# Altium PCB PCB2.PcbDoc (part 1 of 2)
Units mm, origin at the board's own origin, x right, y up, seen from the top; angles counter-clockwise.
Board outline 200 x 180 mm, 2 copper layers (Top Layer, Bottom Layer); 324 components, 291 nets, 661 pads, 0 vias.
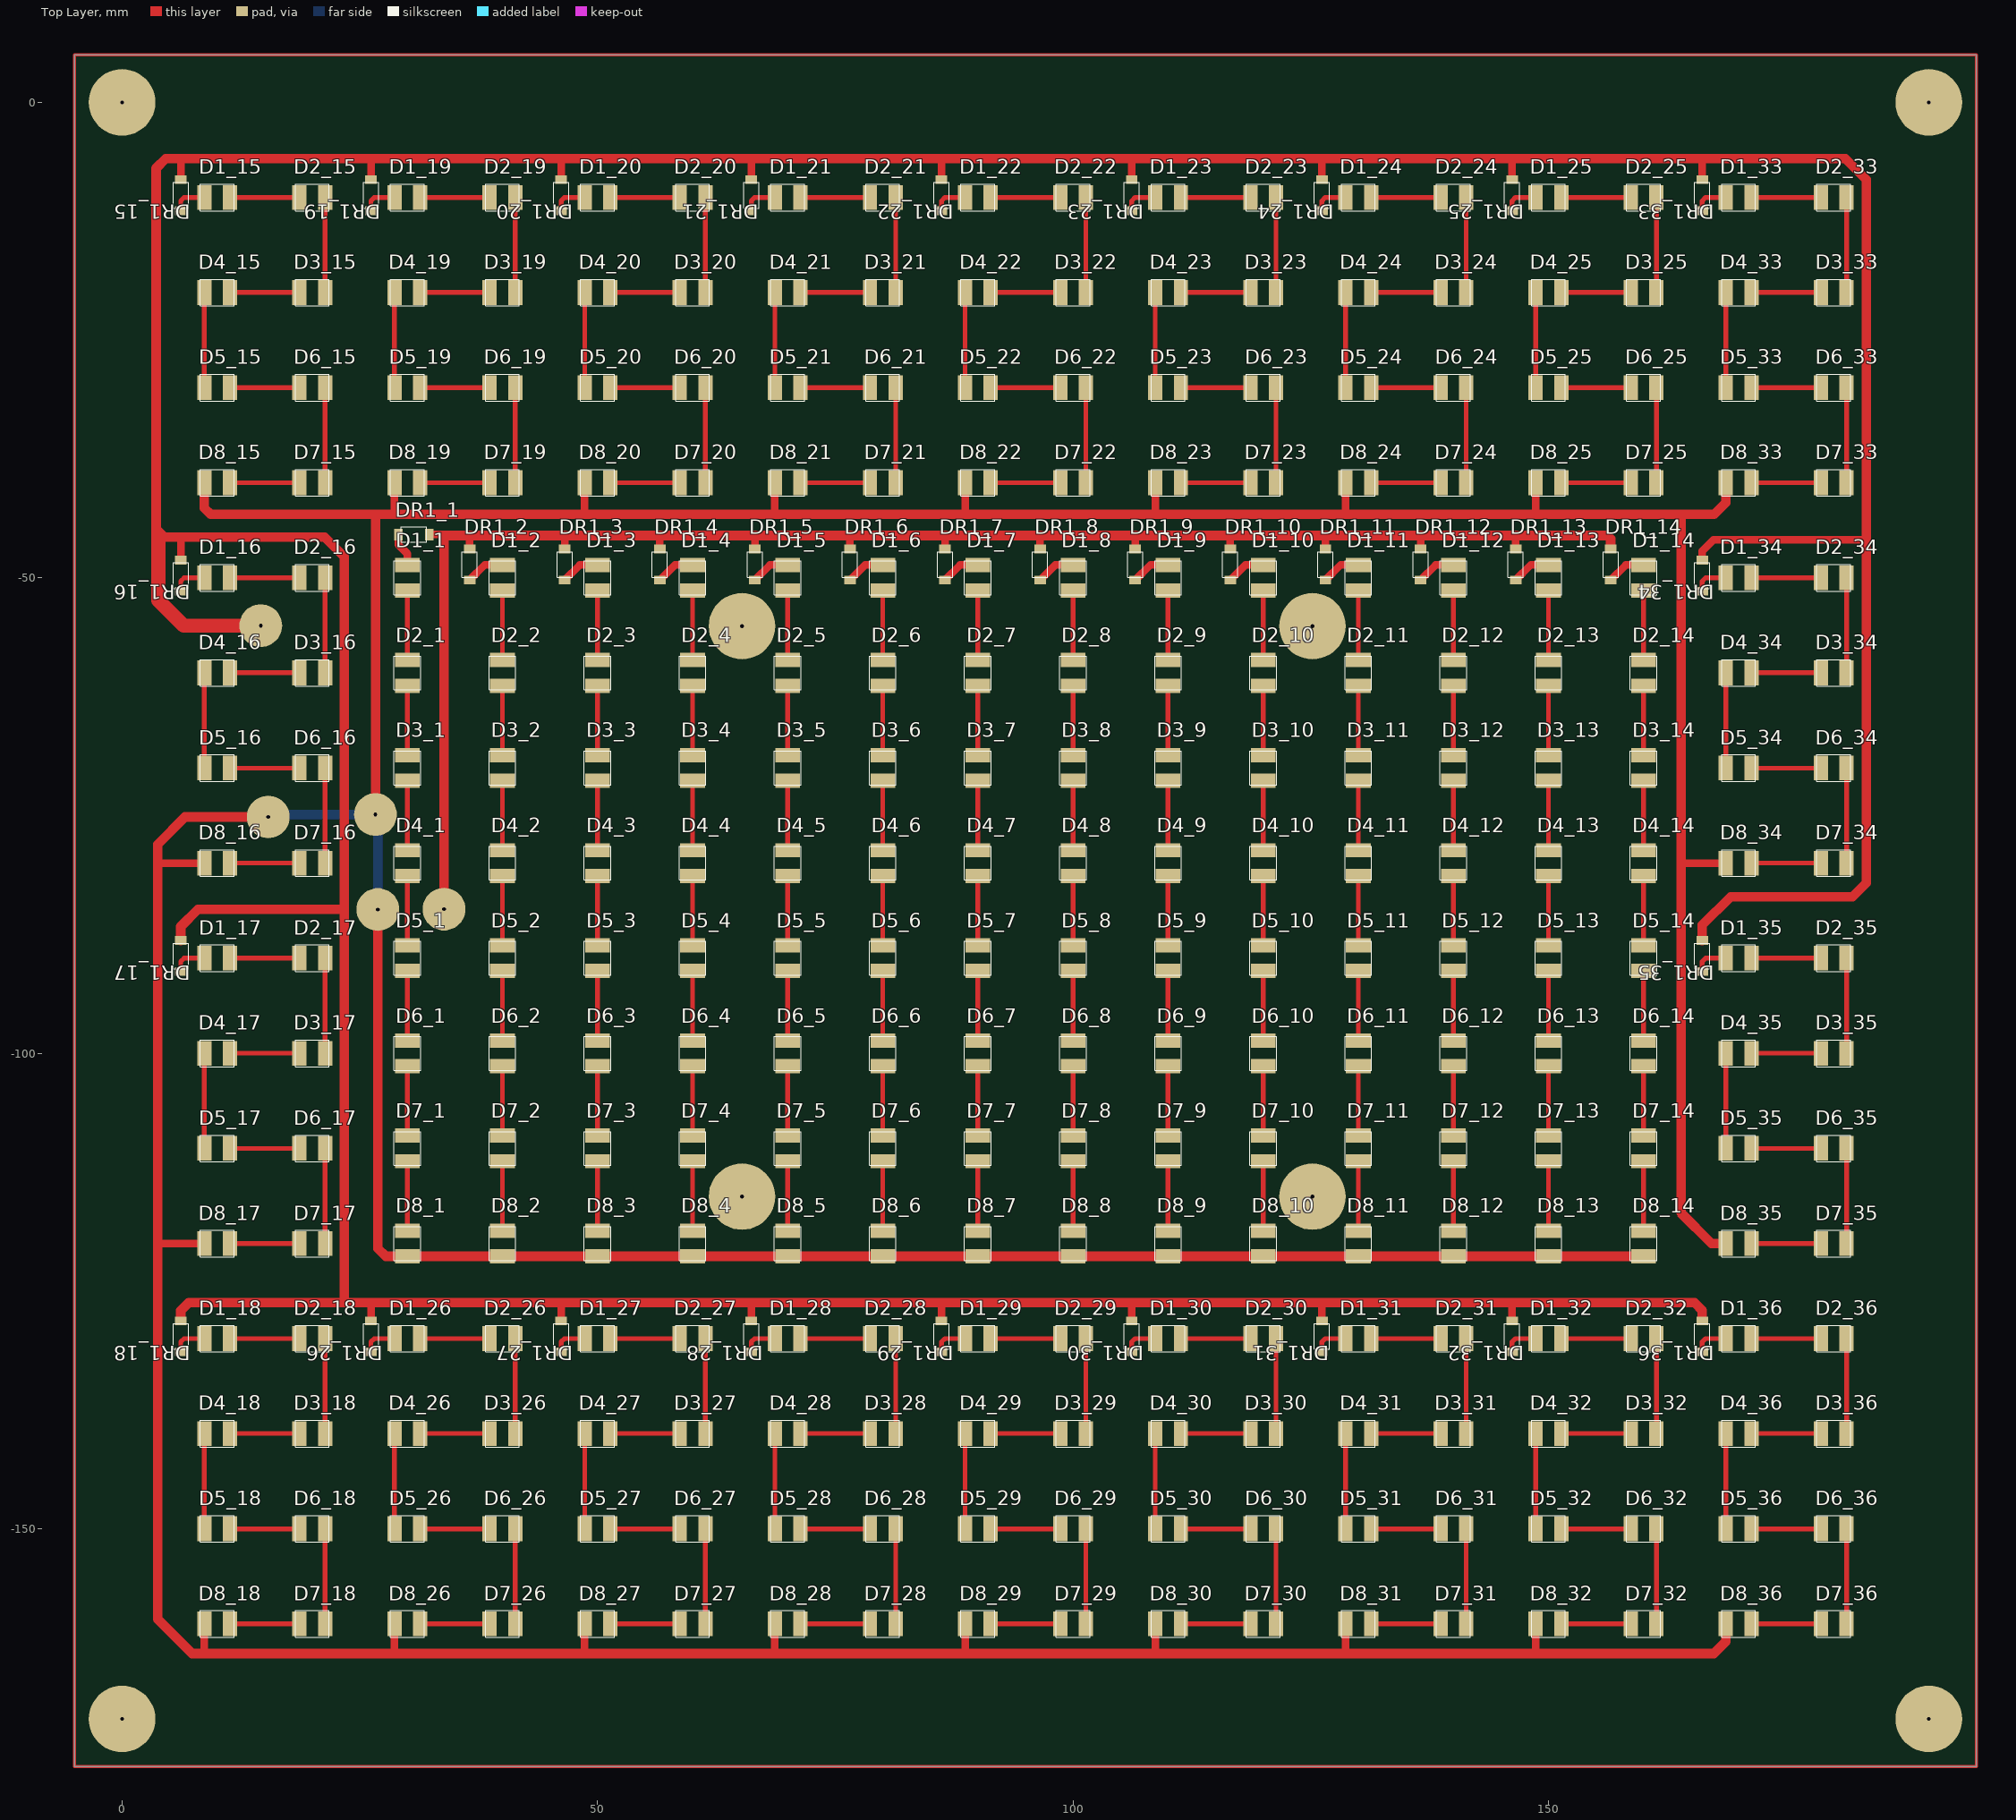
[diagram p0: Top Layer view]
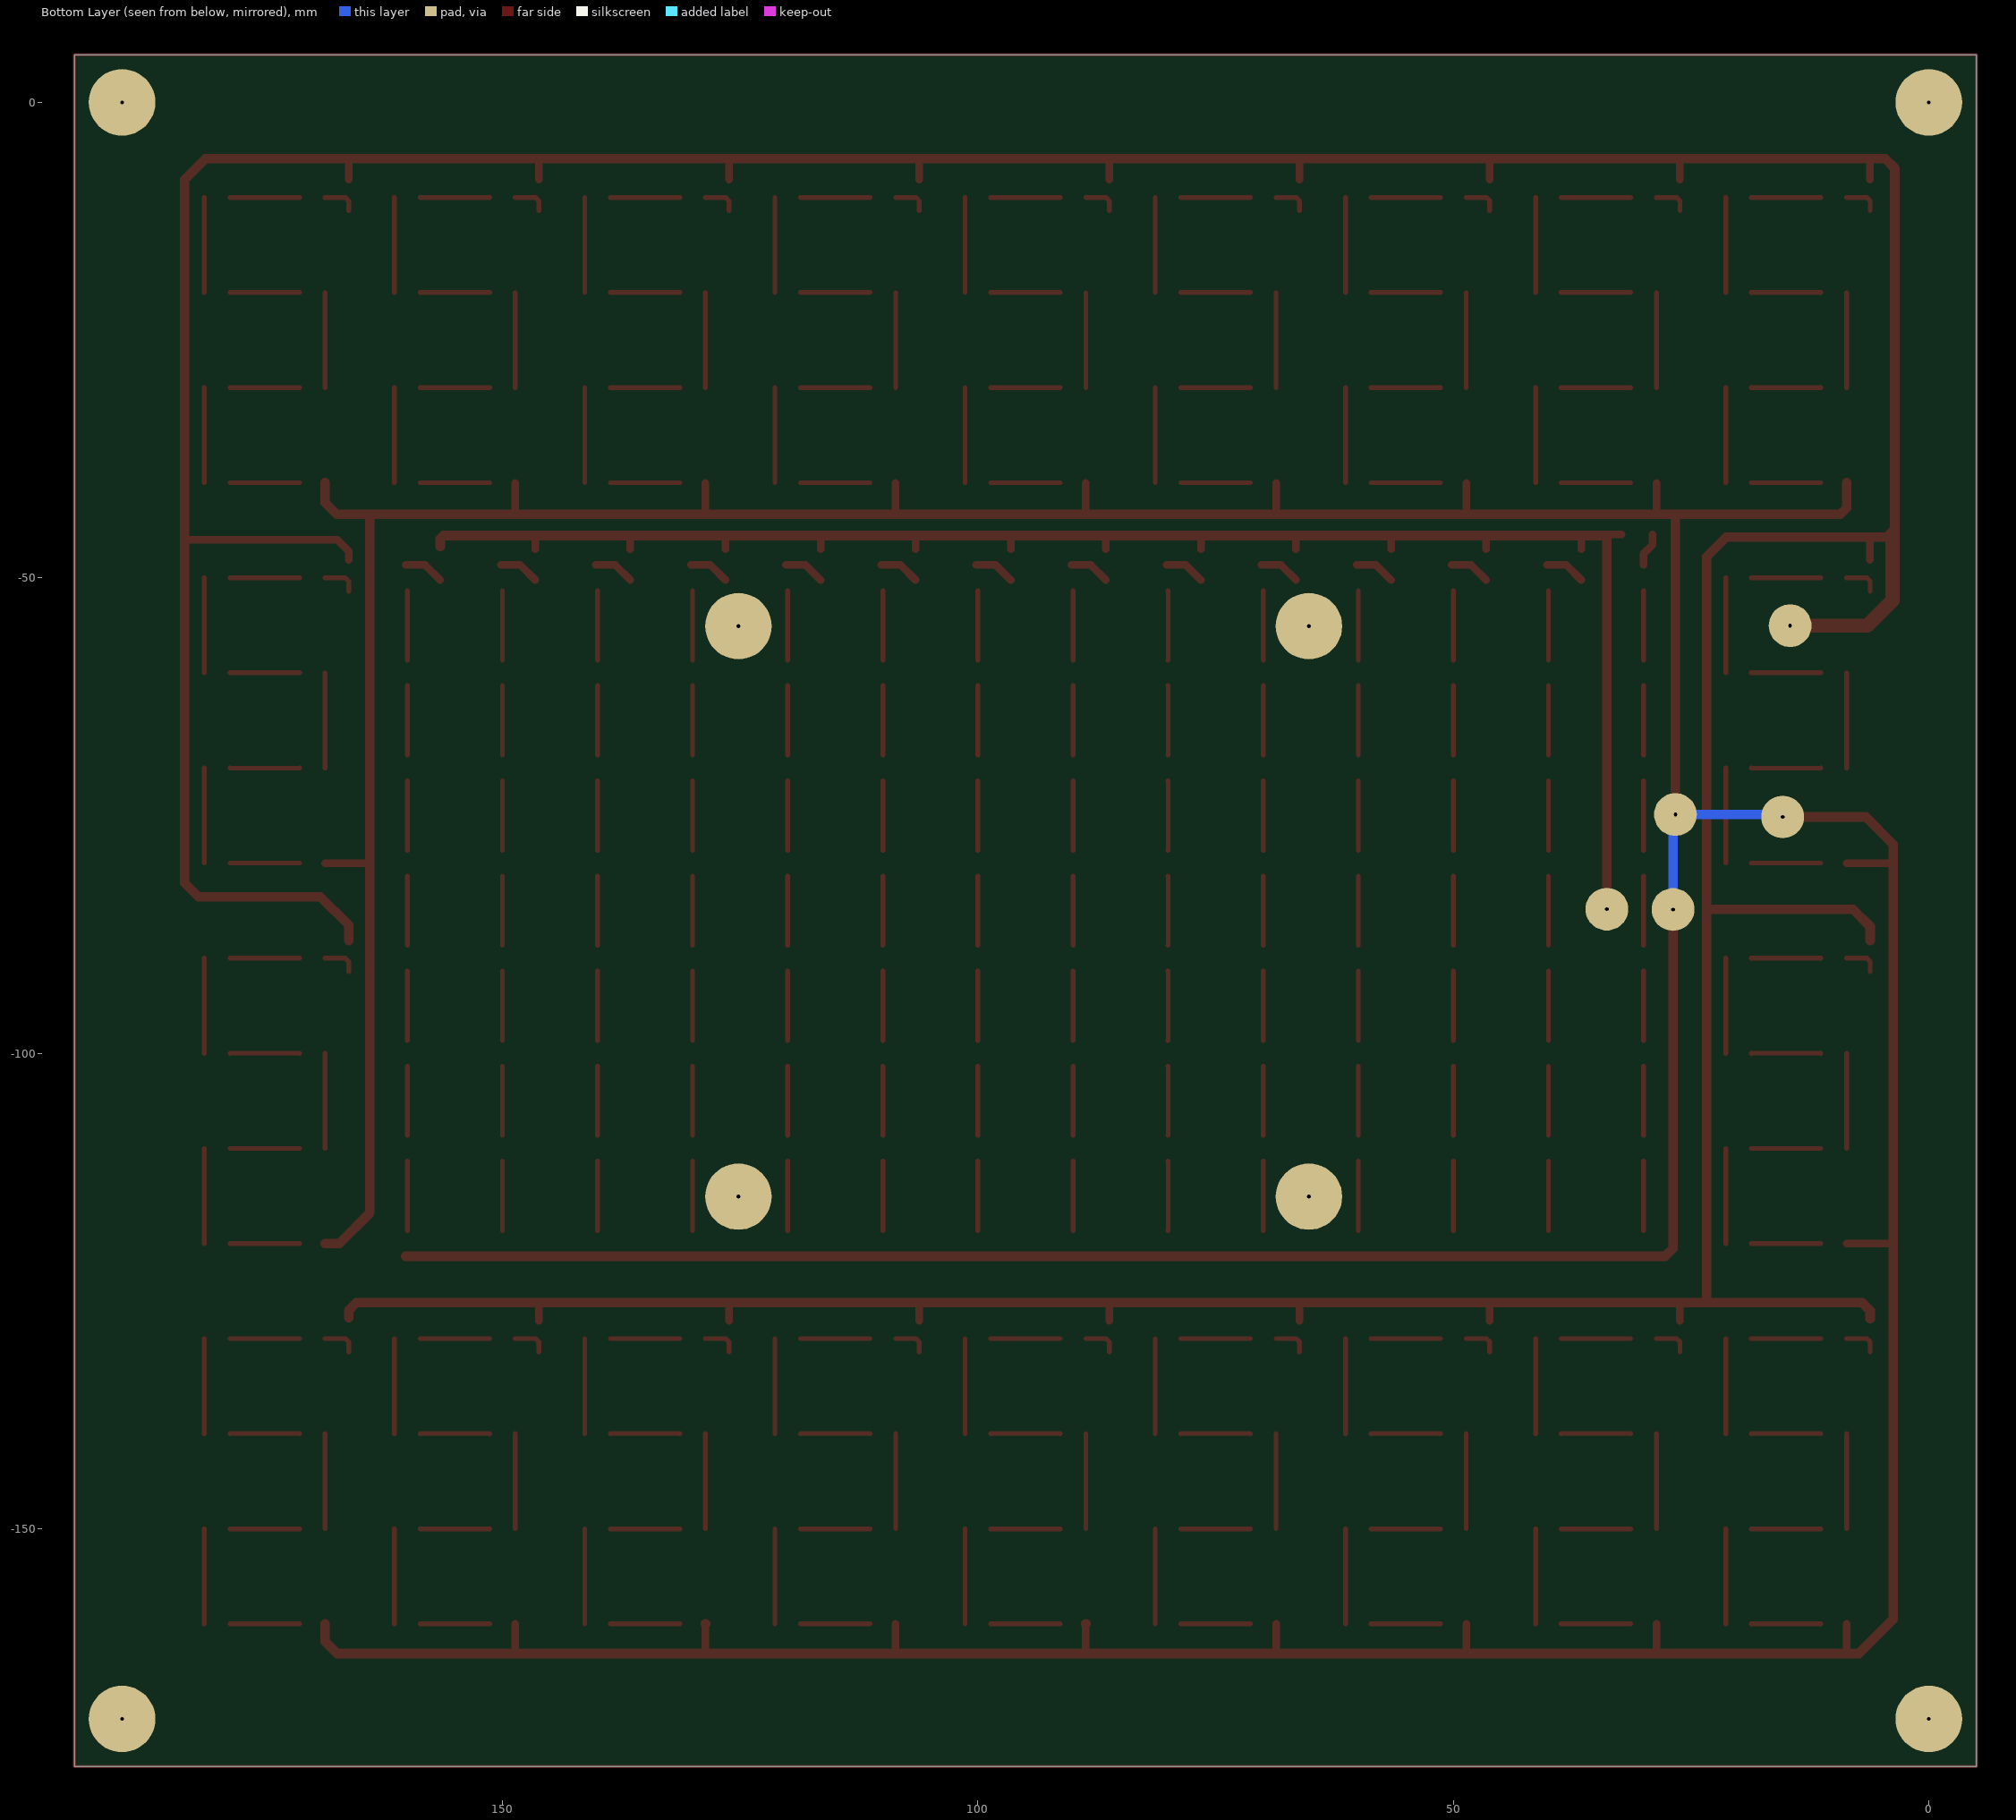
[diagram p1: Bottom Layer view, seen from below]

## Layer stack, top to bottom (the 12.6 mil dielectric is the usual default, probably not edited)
Top Solder: solder mask 0.0102, Solder Resist, Dk 3.5
Top Layer: signal copper 0.0356
Dielectric 1: dielectric 0.32, FR-4, Dk 4.8
Bottom Layer: signal copper 0.0356
Bottom Solder: solder mask 0.0102, Solder Resist, Dk 3.5

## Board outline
195,5 195,-175 -5,-175 -5,5

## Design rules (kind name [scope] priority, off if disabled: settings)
Clearance [All] p1: gap=0.254
PolygonConnect [All] p1: connectstyle=Relief reliefconductorwidth=0.254 reliefentries=4 polygonreliefangle="90 Angle" airgapwidth=0.254
RoomDefinition 36 [InComponentClass('36')] p1: confinementstyle=ConfineIn formatcopy=TRUE lockcomponents=FALSE outline 164.939,-161.797 182.592,-161.797 182.592,-128.371 164.939,-128.371
RoomDefinition 35 [InComponentClass('35')] p2: confinementstyle=ConfineIn formatcopy=TRUE lockcomponents=FALSE outline 164.939,-121.797 182.592,-121.797 182.592,-88.371 164.939,-88.371
RoomDefinition 34 [InComponentClass('34')] p3: confinementstyle=ConfineIn formatcopy=TRUE lockcomponents=FALSE outline 164.939,-81.797 182.592,-81.797 182.592,-48.371 164.939,-48.371
RoomDefinition 33 [InComponentClass('33')] p4: confinementstyle=ConfineIn formatcopy=TRUE lockcomponents=FALSE outline 164.939,-41.797 182.592,-41.797 182.592,-8.371 164.939,-8.371
RoomDefinition 32 [InComponentClass('32')] p5: confinementstyle=ConfineIn formatcopy=TRUE lockcomponents=FALSE outline 144.939,-161.797 162.592,-161.797 162.592,-128.371 144.939,-128.371
RoomDefinition 31 [InComponentClass('31')] p6: confinementstyle=ConfineIn formatcopy=TRUE lockcomponents=FALSE outline 124.939,-161.797 142.592,-161.797 142.592,-128.371 124.939,-128.371
RoomDefinition 30 [InComponentClass('30')] p7: confinementstyle=ConfineIn formatcopy=TRUE lockcomponents=FALSE outline 104.939,-161.797 122.592,-161.797 122.592,-128.371 104.939,-128.371
RoomDefinition 29 [InComponentClass('29')] p8: confinementstyle=ConfineIn formatcopy=TRUE lockcomponents=FALSE outline 84.939,-161.797 102.592,-161.797 102.592,-128.371 84.939,-128.371
RoomDefinition 28 [InComponentClass('28')] p9: confinementstyle=ConfineIn formatcopy=TRUE lockcomponents=FALSE outline 64.939,-161.797 82.592,-161.797 82.592,-128.371 64.939,-128.371
RoomDefinition 27 [InComponentClass('27')] p10: confinementstyle=ConfineIn formatcopy=TRUE lockcomponents=FALSE outline 44.939,-161.797 62.592,-161.797 62.592,-128.371 44.939,-128.371
RoomDefinition 26 [InComponentClass('26')] p11: confinementstyle=ConfineIn formatcopy=TRUE lockcomponents=FALSE outline 24.939,-161.797 42.592,-161.797 42.592,-128.371 24.939,-128.371
RoomDefinition 25 [InComponentClass('25')] p12: confinementstyle=ConfineIn formatcopy=TRUE lockcomponents=FALSE outline 144.939,-41.797 162.592,-41.797 162.592,-8.371 144.939,-8.371
RoomDefinition 24 [InComponentClass('24')] p13: confinementstyle=ConfineIn formatcopy=TRUE lockcomponents=FALSE outline 124.939,-41.797 142.592,-41.797 142.592,-8.371 124.939,-8.371
RoomDefinition 23 [InComponentClass('23')] p14: confinementstyle=ConfineIn formatcopy=TRUE lockcomponents=FALSE outline 104.939,-41.797 122.592,-41.797 122.592,-8.371 104.939,-8.371
RoomDefinition 22 [InComponentClass('22')] p15: confinementstyle=ConfineIn formatcopy=TRUE lockcomponents=FALSE outline 84.939,-41.797 102.592,-41.797 102.592,-8.371 84.939,-8.371
RoomDefinition 21 [InComponentClass('21')] p16: confinementstyle=ConfineIn formatcopy=TRUE lockcomponents=FALSE outline 64.939,-41.797 82.592,-41.797 82.592,-8.371 64.939,-8.371
RoomDefinition 20 [InComponentClass('20')] p17: confinementstyle=ConfineIn formatcopy=TRUE lockcomponents=FALSE outline 44.939,-41.797 62.592,-41.797 62.592,-8.371 44.939,-8.371
RoomDefinition 19 [InComponentClass('19')] p18: confinementstyle=ConfineIn formatcopy=TRUE lockcomponents=FALSE outline 24.939,-41.797 42.592,-41.797 42.592,-8.371 24.939,-8.371
RoomDefinition 18 [InComponentClass('18')] p19: confinementstyle=ConfineIn formatcopy=TRUE lockcomponents=FALSE outline 4.939,-161.797 22.592,-161.797 22.592,-128.371 4.939,-128.371
RoomDefinition 17 [InComponentClass('17')] p20: confinementstyle=ConfineIn formatcopy=TRUE lockcomponents=FALSE outline 4.939,-121.797 22.592,-121.797 22.592,-88.371 4.939,-88.371
RoomDefinition 16 [InComponentClass('16')] p21: confinementstyle=ConfineIn formatcopy=TRUE lockcomponents=FALSE outline 4.939,-81.797 22.592,-81.797 22.592,-48.371 4.939,-48.371
RoomDefinition 15 [InComponentClass('15')] p22: confinementstyle=ConfineIn formatcopy=TRUE lockcomponents=FALSE outline 4.939,-41.797 22.592,-41.797 22.592,-8.371 4.939,-8.371
RoomDefinition 14 [InComponentClass('14')] p23: confinementstyle=ConfineIn formatcopy=TRUE lockcomponents=FALSE outline 155.403,-121.571 162.436,-121.571 162.436,-46.266 155.403,-46.266
RoomDefinition 13 [InComponentClass('13')] p24: confinementstyle=ConfineIn formatcopy=TRUE lockcomponents=FALSE outline 145.403,-121.571 152.436,-121.571 152.436,-46.266 145.403,-46.266
RoomDefinition 12 [InComponentClass('12')] p25: confinementstyle=ConfineIn formatcopy=TRUE lockcomponents=FALSE outline 135.403,-121.571 142.436,-121.571 142.436,-46.266 135.403,-46.266
RoomDefinition 11 [InComponentClass('11')] p26: confinementstyle=ConfineIn formatcopy=TRUE lockcomponents=FALSE outline 125.403,-121.571 132.436,-121.571 132.436,-46.266 125.403,-46.266
RoomDefinition 10 [InComponentClass('10')] p27: confinementstyle=ConfineIn formatcopy=TRUE lockcomponents=FALSE outline 115.403,-121.571 122.436,-121.571 122.436,-46.266 115.403,-46.266
RoomDefinition 9 [InComponentClass('9')] p28: confinementstyle=ConfineIn formatcopy=TRUE lockcomponents=FALSE outline 105.403,-121.571 112.436,-121.571 112.436,-46.266 105.403,-46.266
RoomDefinition 8 [InComponentClass('8')] p29: confinementstyle=ConfineIn formatcopy=TRUE lockcomponents=FALSE outline 95.403,-121.571 102.436,-121.571 102.436,-46.266 95.403,-46.266
RoomDefinition 7 [InComponentClass('7')] p30: confinementstyle=ConfineIn formatcopy=TRUE lockcomponents=FALSE outline 85.403,-121.571 92.436,-121.571 92.436,-46.266 85.403,-46.266
RoomDefinition 6 [InComponentClass('6')] p31: confinementstyle=ConfineIn formatcopy=TRUE lockcomponents=FALSE outline 75.403,-121.571 82.436,-121.571 82.436,-46.266 75.403,-46.266
RoomDefinition 5 [InComponentClass('5')] p32: confinementstyle=ConfineIn formatcopy=TRUE lockcomponents=FALSE outline 65.403,-121.571 72.436,-121.571 72.436,-46.266 65.403,-46.266
RoomDefinition 4 [InComponentClass('4')] p33: confinementstyle=ConfineIn formatcopy=TRUE lockcomponents=FALSE outline 55.403,-121.571 62.436,-121.571 62.436,-46.266 55.403,-46.266
RoomDefinition 3 [InComponentClass('3')] p34: confinementstyle=ConfineIn formatcopy=TRUE lockcomponents=FALSE outline 45.403,-121.571 52.436,-121.571 52.436,-46.266 45.403,-46.266
RoomDefinition 2 [InComponentClass('2')] p35: confinementstyle=ConfineIn formatcopy=TRUE lockcomponents=FALSE outline 35.403,-121.571 42.436,-121.571 42.436,-46.266 35.403,-46.266
RoomDefinition 1 [InComponentClass('1')] p36: confinementstyle=ConfineIn formatcopy=TRUE lockcomponents=FALSE outline 25.403,-121.571 32.436,-121.571 32.436,-46.266 25.403,-46.266
RoutingVias [All] p1: holewidth=0.711 width=1.27 viastyle="Through Hole" minholewidth=0.711 minwidth=1.27 maxholewidth=0.711 maxwidth=1.27
SolderMaskExpansion [All] p1: expansion=0.102
Width [All] p1: maxlimit=1.5 minlimit=0.2 preferedwidth=0.4
30 further rules are at their usual default settings.

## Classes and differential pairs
channel class PCB: 1 2 3 4 5 6 7 8 9 10 11 12 13 14 15 16 17 18 19 20 21 22 23 24 25 26 27 28 29 30 31 32 33 34 35 36
component class 36: D1_36 D2_36 D3_36 D4_36 D5_36 D6_36 D7_36 D8_36 DR1_36
component class 35: D1_35 D2_35 D3_35 D4_35 D5_35 D6_35 D7_35 D8_35 DR1_35
component class 34: D1_34 D2_34 D3_34 D4_34 D5_34 D6_34 D7_34 D8_34 DR1_34
component class 33: D1_33 D2_33 D3_33 D4_33 D5_33 D6_33 D7_33 D8_33 DR1_33
component class 32: D1_32 D2_32 D3_32 D4_32 D5_32 D6_32 D7_32 D8_32 DR1_32
component class 31: D1_31 D2_31 D3_31 D4_31 D5_31 D6_31 D7_31 D8_31 DR1_31
component class 30: D1_30 D2_30 D3_30 D4_30 D5_30 D6_30 D7_30 D8_30 DR1_30
component class 29: D1_29 D2_29 D3_29 D4_29 D5_29 D6_29 D7_29 D8_29 DR1_29
component class 28: D1_28 D2_28 D3_28 D4_28 D5_28 D6_28 D7_28 D8_28 DR1_28
component class 27: D1_27 D2_27 D3_27 D4_27 D5_27 D6_27 D7_27 D8_27 DR1_27
component class 26: D1_26 D2_26 D3_26 D4_26 D5_26 D6_26 D7_26 D8_26 DR1_26
component class 25: D1_25 D2_25 D3_25 D4_25 D5_25 D6_25 D7_25 D8_25 DR1_25
component class 24: D1_24 D2_24 D3_24 D4_24 D5_24 D6_24 D7_24 D8_24 DR1_24
component class 23: D1_23 D2_23 D3_23 D4_23 D5_23 D6_23 D7_23 D8_23 DR1_23
component class 22: D1_22 D2_22 D3_22 D4_22 D5_22 D6_22 D7_22 D8_22 DR1_22
component class 21: D1_21 D2_21 D3_21 D4_21 D5_21 D6_21 D7_21 D8_21 DR1_21
component class 20: D1_20 D2_20 D3_20 D4_20 D5_20 D6_20 D7_20 D8_20 DR1_20
component class 19: D1_19 D2_19 D3_19 D4_19 D5_19 D6_19 D7_19 D8_19 DR1_19
component class 18: D1_18 D2_18 D3_18 D4_18 D5_18 D6_18 D7_18 D8_18 DR1_18
component class 17: D1_17 D2_17 D3_17 D4_17 D5_17 D6_17 D7_17 D8_17 DR1_17
component class 16: D1_16 D2_16 D3_16 D4_16 D5_16 D6_16 D7_16 D8_16 DR1_16
component class 15: D1_15 D2_15 D3_15 D4_15 D5_15 D6_15 D7_15 D8_15 DR1_15
component class 14: D1_14 D2_14 D3_14 D4_14 D5_14 D6_14 D7_14 D8_14 DR1_14
component class 13: D1_13 D2_13 D3_13 D4_13 D5_13 D6_13 D7_13 D8_13 DR1_13
component class 12: D1_12 D2_12 D3_12 D4_12 D5_12 D6_12 D7_12 D8_12 DR1_12
component class 11: D1_11 D2_11 D3_11 D4_11 D5_11 D6_11 D7_11 D8_11 DR1_11
component class 10: D1_10 D2_10 D3_10 D4_10 D5_10 D6_10 D7_10 D8_10 DR1_10
component class 9: D1_9 D2_9 D3_9 D4_9 D5_9 D6_9 D7_9 D8_9 DR1_9
component class 8: D1_8 D2_8 D3_8 D4_8 D5_8 D6_8 D7_8 D8_8 DR1_8
component class 7: D1_7 D2_7 D3_7 D4_7 D5_7 D6_7 D7_7 D8_7 DR1_7
component class 6: D1_6 D2_6 D3_6 D4_6 D5_6 D6_6 D7_6 D8_6 DR1_6
component class 5: D1_5 D2_5 D3_5 D4_5 D5_5 D6_5 D7_5 D8_5 DR1_5
component class 4: D1_4 D2_4 D3_4 D4_4 D5_4 D6_4 D7_4 D8_4 DR1_4
component class 3: D1_3 D2_3 D3_3 D4_3 D5_3 D6_3 D7_3 D8_3 DR1_3
component class 2: D1_2 D2_2 D3_2 D4_2 D5_2 D6_2 D7_2 D8_2 DR1_2
component class 1: D1_1 D2_1 D3_1 D4_1 D5_1 D6_1 D7_1 D8_1 DR1_1

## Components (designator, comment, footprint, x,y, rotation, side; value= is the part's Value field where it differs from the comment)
D1_1 "LED0" UV_LED 30,-50 r270 top (schematic designator D1)
D1_2 "LED0" UV_LED 40,-50 r270 top (schematic designator D1)
D1_3 "LED0" UV_LED 50,-50 r270 top (schematic designator D1)
D1_4 "LED0" UV_LED 60,-50 r270 top (schematic designator D1)
D1_5 "LED0" UV_LED 70,-50 r270 top (schematic designator D1)
D1_6 "LED0" UV_LED 80,-50 r270 top (schematic designator D1)
D1_7 "LED0" UV_LED 90,-50 r270 top (schematic designator D1)
D1_8 "LED0" UV_LED 100,-50 r270 top (schematic designator D1)
D1_9 "LED0" UV_LED 110,-50 r270 top (schematic designator D1)
D1_10 "LED0" UV_LED 120,-50 r270 top (schematic designator D1)
D1_11 "LED0" UV_LED 130,-50 r270 top (schematic designator D1)
D1_12 "LED0" UV_LED 140,-50 r270 top (schematic designator D1)
D1_13 "LED0" UV_LED 150,-50 r270 top (schematic designator D1)
D1_14 "LED0" UV_LED 160,-50 r270 top (schematic designator D1)
D1_15 "LED0" UV_LED 10,-10 r0 top (schematic designator D1)
D1_16 "LED0" UV_LED 10,-50 r0 top (schematic designator D1)
D1_17 "LED0" UV_LED 10,-90 r0 top (schematic designator D1)
D1_18 "LED0" UV_LED 10,-130 r0 top (schematic designator D1)
D1_19 "LED0" UV_LED 30,-10 r0 top (schematic designator D1)
D1_20 "LED0" UV_LED 50,-10 r0 top (schematic designator D1)
D1_21 "LED0" UV_LED 70,-10 r0 top (schematic designator D1)
D1_22 "LED0" UV_LED 90,-10 r0 top (schematic designator D1)
D1_23 "LED0" UV_LED 110,-10 r0 top (schematic designator D1)
D1_24 "LED0" UV_LED 130,-10 r0 top (schematic designator D1)
D1_25 "LED0" UV_LED 150,-10 r0 top (schematic designator D1)
D1_26 "LED0" UV_LED 30,-130 r0 top (schematic designator D1)
D1_27 "LED0" UV_LED 50,-130 r0 top (schematic designator D1)
D1_28 "LED0" UV_LED 70,-130 r0 top (schematic designator D1)
D1_29 "LED0" UV_LED 90,-130 r0 top (schematic designator D1)
D1_30 "LED0" UV_LED 110,-130 r0 top (schematic designator D1)
D1_31 "LED0" UV_LED 130,-130 r0 top (schematic designator D1)
D1_32 "LED0" UV_LED 150,-130 r0 top (schematic designator D1)
D1_33 "LED0" UV_LED 170,-10 r0 top (schematic designator D1)
D1_34 "LED0" UV_LED 170,-50 r0 top (schematic designator D1)
D1_35 "LED0" UV_LED 170,-90 r0 top (schematic designator D1)
D1_36 "LED0" UV_LED 170,-130 r0 top (schematic designator D1)
D2_1 "LED0" UV_LED 30,-60 r270 top (schematic designator D2)
D2_2 "LED0" UV_LED 40,-60 r270 top (schematic designator D2)
D2_3 "LED0" UV_LED 50,-60 r270 top (schematic designator D2)
D2_4 "LED0" UV_LED 60,-60 r270 top (schematic designator D2)
D2_5 "LED0" UV_LED 70,-60 r270 top (schematic designator D2)
D2_6 "LED0" UV_LED 80,-60 r270 top (schematic designator D2)
D2_7 "LED0" UV_LED 90,-60 r270 top (schematic designator D2)
D2_8 "LED0" UV_LED 100,-60 r270 top (schematic designator D2)
D2_9 "LED0" UV_LED 110,-60 r270 top (schematic designator D2)
D2_10 "LED0" UV_LED 120,-60 r270 top (schematic designator D2)
D2_11 "LED0" UV_LED 130,-60 r270 top (schematic designator D2)
D2_12 "LED0" UV_LED 140,-60 r270 top (schematic designator D2)
D2_13 "LED0" UV_LED 150,-60 r270 top (schematic designator D2)
D2_14 "LED0" UV_LED 160,-60 r270 top (schematic designator D2)
D2_15 "LED0" UV_LED 20,-10 r0 top (schematic designator D2)
D2_16 "LED0" UV_LED 20,-50 r0 top (schematic designator D2)
D2_17 "LED0" UV_LED 20,-90 r0 top (schematic designator D2)
D2_18 "LED0" UV_LED 20,-130 r0 top (schematic designator D2)
D2_19 "LED0" UV_LED 40,-10 r0 top (schematic designator D2)
D2_20 "LED0" UV_LED 60,-10 r0 top (schematic designator D2)
D2_21 "LED0" UV_LED 80,-10 r0 top (schematic designator D2)
D2_22 "LED0" UV_LED 100,-10 r0 top (schematic designator D2)
D2_23 "LED0" UV_LED 120,-10 r0 top (schematic designator D2)
D2_24 "LED0" UV_LED 140,-10 r0 top (schematic designator D2)
D2_25 "LED0" UV_LED 160,-10 r0 top (schematic designator D2)
D2_26 "LED0" UV_LED 40,-130 r0 top (schematic designator D2)
D2_27 "LED0" UV_LED 60,-130 r0 top (schematic designator D2)
D2_28 "LED0" UV_LED 80,-130 r0 top (schematic designator D2)
D2_29 "LED0" UV_LED 100,-130 r0 top (schematic designator D2)
D2_30 "LED0" UV_LED 120,-130 r0 top (schematic designator D2)
D2_31 "LED0" UV_LED 140,-130 r0 top (schematic designator D2)
D2_32 "LED0" UV_LED 160,-130 r0 top (schematic designator D2)
D2_33 "LED0" UV_LED 180,-10 r0 top (schematic designator D2)
D2_34 "LED0" UV_LED 180,-50 r0 top (schematic designator D2)
D2_35 "LED0" UV_LED 180,-90 r0 top (schematic designator D2)
D2_36 "LED0" UV_LED 180,-130 r0 top (schematic designator D2)
D3_1 "LED0" UV_LED 30,-70 r270 top (schematic designator D3)
D3_2 "LED0" UV_LED 40,-70 r270 top (schematic designator D3)
D3_3 "LED0" UV_LED 50,-70 r270 top (schematic designator D3)
D3_4 "LED0" UV_LED 60,-70 r270 top (schematic designator D3)
D3_5 "LED0" UV_LED 70,-70 r270 top (schematic designator D3)
D3_6 "LED0" UV_LED 80,-70 r270 top (schematic designator D3)
D3_7 "LED0" UV_LED 90,-70 r270 top (schematic designator D3)
D3_8 "LED0" UV_LED 100,-70 r270 top (schematic designator D3)
D3_9 "LED0" UV_LED 110,-70 r270 top (schematic designator D3)
D3_10 "LED0" UV_LED 120,-70 r270 top (schematic designator D3)
D3_11 "LED0" UV_LED 130,-70 r270 top (schematic designator D3)
D3_12 "LED0" UV_LED 140,-70 r270 top (schematic designator D3)
D3_13 "LED0" UV_LED 150,-70 r270 top (schematic designator D3)
D3_14 "LED0" UV_LED 160,-70 r270 top (schematic designator D3)
D3_15 "LED0" UV_LED 20,-20 r180 top (schematic designator D3)
D3_16 "LED0" UV_LED 20,-60 r180 top (schematic designator D3)
D3_17 "LED0" UV_LED 20,-100 r180 top (schematic designator D3)
D3_18 "LED0" UV_LED 20,-140 r180 top (schematic designator D3)
D3_19 "LED0" UV_LED 40,-20 r180 top (schematic designator D3)
D3_20 "LED0" UV_LED 60,-20 r180 top (schematic designator D3)
D3_21 "LED0" UV_LED 80,-20 r180 top (schematic designator D3)
D3_22 "LED0" UV_LED 100,-20 r180 top (schematic designator D3)
D3_23 "LED0" UV_LED 120,-20 r180 top (schematic designator D3)
D3_24 "LED0" UV_LED 140,-20 r180 top (schematic designator D3)
D3_25 "LED0" UV_LED 160,-20 r180 top (schematic designator D3)
D3_26 "LED0" UV_LED 40,-140 r180 top (schematic designator D3)
D3_27 "LED0" UV_LED 60,-140 r180 top (schematic designator D3)
D3_28 "LED0" UV_LED 80,-140 r180 top (schematic designator D3)
D3_29 "LED0" UV_LED 100,-140 r180 top (schematic designator D3)
D3_30 "LED0" UV_LED 120,-140 r180 top (schematic designator D3)
D3_31 "LED0" UV_LED 140,-140 r180 top (schematic designator D3)
D3_32 "LED0" UV_LED 160,-140 r180 top (schematic designator D3)
D3_33 "LED0" UV_LED 180,-20 r180 top (schematic designator D3)
D3_34 "LED0" UV_LED 180,-60 r180 top (schematic designator D3)
D3_35 "LED0" UV_LED 180,-100 r180 top (schematic designator D3)
D3_36 "LED0" UV_LED 180,-140 r180 top (schematic designator D3)
D4_1 "LED0" UV_LED 30,-80 r270 top (schematic designator D4)
D4_2 "LED0" UV_LED 40,-80 r270 top (schematic designator D4)
D4_3 "LED0" UV_LED 50,-80 r270 top (schematic designator D4)
D4_4 "LED0" UV_LED 60,-80 r270 top (schematic designator D4)
D4_5 "LED0" UV_LED 70,-80 r270 top (schematic designator D4)
D4_6 "LED0" UV_LED 80,-80 r270 top (schematic designator D4)
D4_7 "LED0" UV_LED 90,-80 r270 top (schematic designator D4)
D4_8 "LED0" UV_LED 100,-80 r270 top (schematic designator D4)
D4_9 "LED0" UV_LED 110,-80 r270 top (schematic designator D4)
D4_10 "LED0" UV_LED 120,-80 r270 top (schematic designator D4)
D4_11 "LED0" UV_LED 130,-80 r270 top (schematic designator D4)
D4_12 "LED0" UV_LED 140,-80 r270 top (schematic designator D4)
D4_13 "LED0" UV_LED 150,-80 r270 top (schematic designator D4)
D4_14 "LED0" UV_LED 160,-80 r270 top (schematic designator D4)
D4_15 "LED0" UV_LED 10,-20 r180 top (schematic designator D4)
D4_16 "LED0" UV_LED 10,-60 r180 top (schematic designator D4)
D4_17 "LED0" UV_LED 10,-100 r180 top (schematic designator D4)
D4_18 "LED0" UV_LED 10,-140 r180 top (schematic designator D4)
D4_19 "LED0" UV_LED 30,-20 r180 top (schematic designator D4)
D4_20 "LED0" UV_LED 50,-20 r180 top (schematic designator D4)
D4_21 "LED0" UV_LED 70,-20 r180 top (schematic designator D4)
D4_22 "LED0" UV_LED 90,-20 r180 top (schematic designator D4)
D4_23 "LED0" UV_LED 110,-20 r180 top (schematic designator D4)
D4_24 "LED0" UV_LED 130,-20 r180 top (schematic designator D4)
D4_25 "LED0" UV_LED 150,-20 r180 top (schematic designator D4)
D4_26 "LED0" UV_LED 30,-140 r180 top (schematic designator D4)
D4_27 "LED0" UV_LED 50,-140 r180 top (schematic designator D4)
D4_28 "LED0" UV_LED 70,-140 r180 top (schematic designator D4)
D4_29 "LED0" UV_LED 90,-140 r180 top (schematic designator D4)
D4_30 "LED0" UV_LED 110,-140 r180 top (schematic designator D4)
D4_31 "LED0" UV_LED 130,-140 r180 top (schematic designator D4)
D4_32 "LED0" UV_LED 150,-140 r180 top (schematic designator D4)
D4_33 "LED0" UV_LED 170,-20 r180 top (schematic designator D4)
D4_34 "LED0" UV_LED 170,-60 r180 top (schematic designator D4)
D4_35 "LED0" UV_LED 170,-100 r180 top (schematic designator D4)
D4_36 "LED0" UV_LED 170,-140 r180 top (schematic designator D4)
D5_1 "LED0" UV_LED 30,-90 r270 top (schematic designator D5)
D5_2 "LED0" UV_LED 40,-90 r270 top (schematic designator D5)
D5_3 "LED0" UV_LED 50,-90 r270 top (schematic designator D5)
D5_4 "LED0" UV_LED 60,-90 r270 top (schematic designator D5)
D5_5 "LED0" UV_LED 70,-90 r270 top (schematic designator D5)
D5_6 "LED0" UV_LED 80,-90 r270 top (schematic designator D5)
D5_7 "LED0" UV_LED 90,-90 r270 top (schematic designator D5)
D5_8 "LED0" UV_LED 100,-90 r270 top (schematic designator D5)
D5_9 "LED0" UV_LED 110,-90 r270 top (schematic designator D5)
D5_10 "LED0" UV_LED 120,-90 r270 top (schematic designator D5)
D5_11 "LED0" UV_LED 130,-90 r270 top (schematic designator D5)
D5_12 "LED0" UV_LED 140,-90 r270 top (schematic designator D5)
D5_13 "LED0" UV_LED 150,-90 r270 top (schematic designator D5)
D5_14 "LED0" UV_LED 160,-90 r270 top (schematic designator D5)
D5_15 "LED0" UV_LED 10,-30 r0 top (schematic designator D5)
D5_16 "LED0" UV_LED 10,-70 r0 top (schematic designator D5)
D5_17 "LED0" UV_LED 10,-110 r0 top (schematic designator D5)
D5_18 "LED0" UV_LED 10,-150 r0 top (schematic designator D5)
D5_19 "LED0" UV_LED 30,-30 r0 top (schematic designator D5)
D5_20 "LED0" UV_LED 50,-30 r0 top (schematic designator D5)
D5_21 "LED0" UV_LED 70,-30 r0 top (schematic designator D5)
D5_22 "LED0" UV_LED 90,-30 r0 top (schematic designator D5)
D5_23 "LED0" UV_LED 110,-30 r0 top (schematic designator D5)
D5_24 "LED0" UV_LED 130,-30 r0 top (schematic designator D5)
D5_25 "LED0" UV_LED 150,-30 r0 top (schematic designator D5)
D5_26 "LED0" UV_LED 30,-150 r0 top (schematic designator D5)
D5_27 "LED0" UV_LED 50,-150 r0 top (schematic designator D5)
D5_28 "LED0" UV_LED 70,-150 r0 top (schematic designator D5)
D5_29 "LED0" UV_LED 90,-150 r0 top (schematic designator D5)
D5_30 "LED0" UV_LED 110,-150 r0 top (schematic designator D5)
D5_31 "LED0" UV_LED 130,-150 r0 top (schematic designator D5)
D5_32 "LED0" UV_LED 150,-150 r0 top (schematic designator D5)
D5_33 "LED0" UV_LED 170,-30 r0 top (schematic designator D5)
D5_34 "LED0" UV_LED 170,-70 r0 top (schematic designator D5)
D5_35 "LED0" UV_LED 170,-110 r0 top (schematic designator D5)
D5_36 "LED0" UV_LED 170,-150 r0 top (schematic designator D5)
D6_1 "LED0" UV_LED 30,-100 r270 top (schematic designator D6)
D6_2 "LED0" UV_LED 40,-100 r270 top (schematic designator D6)
D6_3 "LED0" UV_LED 50,-100 r270 top (schematic designator D6)
D6_4 "LED0" UV_LED 60,-100 r270 top (schematic designator D6)
D6_5 "LED0" UV_LED 70,-100 r270 top (schematic designator D6)
D6_6 "LED0" UV_LED 80,-100 r270 top (schematic designator D6)
D6_7 "LED0" UV_LED 90,-100 r270 top (schematic designator D6)
D6_8 "LED0" UV_LED 100,-100 r270 top (schematic designator D6)
D6_9 "LED0" UV_LED 110,-100 r270 top (schematic designator D6)
D6_10 "LED0" UV_LED 120,-100 r270 top (schematic designator D6)
D6_11 "LED0" UV_LED 130,-100 r270 top (schematic designator D6)
D6_12 "LED0" UV_LED 140,-100 r270 top (schematic designator D6)
D6_13 "LED0" UV_LED 150,-100 r270 top (schematic designator D6)
D6_14 "LED0" UV_LED 160,-100 r270 top (schematic designator D6)
D6_15 "LED0" UV_LED 20,-30 r0 top (schematic designator D6)
D6_16 "LED0" UV_LED 20,-70 r0 top (schematic designator D6)
D6_17 "LED0" UV_LED 20,-110 r0 top (schematic designator D6)
D6_18 "LED0" UV_LED 20,-150 r0 top (schematic designator D6)
D6_19 "LED0" UV_LED 40,-30 r0 top (schematic designator D6)
D6_20 "LED0" UV_LED 60,-30 r0 top (schematic designator D6)
D6_21 "LED0" UV_LED 80,-30 r0 top (schematic designator D6)
D6_22 "LED0" UV_LED 100,-30 r0 top (schematic designator D6)
D6_23 "LED0" UV_LED 120,-30 r0 top (schematic designator D6)
D6_24 "LED0" UV_LED 140,-30 r0 top (schematic designator D6)
D6_25 "LED0" UV_LED 160,-30 r0 top (schematic designator D6)
D6_26 "LED0" UV_LED 40,-150 r0 top (schematic designator D6)
D6_27 "LED0" UV_LED 60,-150 r0 top (schematic designator D6)
D6_28 "LED0" UV_LED 80,-150 r0 top (schematic designator D6)
D6_29 "LED0" UV_LED 100,-150 r0 top (schematic designator D6)
D6_30 "LED0" UV_LED 120,-150 r0 top (schematic designator D6)
D6_31 "LED0" UV_LED 140,-150 r0 top (schematic designator D6)
D6_32 "LED0" UV_LED 160,-150 r0 top (schematic designator D6)
D6_33 "LED0" UV_LED 180,-30 r0 top (schematic designator D6)
D6_34 "LED0" UV_LED 180,-70 r0 top (schematic designator D6)
D6_35 "LED0" UV_LED 180,-110 r0 top (schematic designator D6)
D6_36 "LED0" UV_LED 180,-150 r0 top (schematic designator D6)
D7_1 "LED0" UV_LED 30,-110 r270 top (schematic designator D7)
D7_2 "LED0" UV_LED 40,-110 r270 top (schematic designator D7)
D7_3 "LED0" UV_LED 50,-110 r270 top (schematic designator D7)
D7_4 "LED0" UV_LED 60,-110 r270 top (schematic designator D7)
D7_5 "LED0" UV_LED 70,-110 r270 top (schematic designator D7)
D7_6 "LED0" UV_LED 80,-110 r270 top (schematic designator D7)
D7_7 "LED0" UV_LED 90,-110 r270 top (schematic designator D7)
D7_8 "LED0" UV_LED 100,-110 r270 top (schematic designator D7)
D7_9 "LED0" UV_LED 110,-110 r270 top (schematic designator D7)
D7_10 "LED0" UV_LED 120,-110 r270 top (schematic designator D7)
D7_11 "LED0" UV_LED 130,-110 r270 top (schematic designator D7)
D7_12 "LED0" UV_LED 140,-110 r270 top (schematic designator D7)
D7_13 "LED0" UV_LED 150,-110 r270 top (schematic designator D7)
D7_14 "LED0" UV_LED 160,-110 r270 top (schematic designator D7)
D7_15 "LED0" UV_LED 20,-40 r180 top (schematic designator D7)
D7_16 "LED0" UV_LED 20,-80 r180 top (schematic designator D7)
D7_17 "LED0" UV_LED 20,-120 r180 top (schematic designator D7)
D7_18 "LED0" UV_LED 20,-160 r180 top (schematic designator D7)
D7_19 "LED0" UV_LED 40,-40 r180 top (schematic designator D7)
D7_20 "LED0" UV_LED 60,-40 r180 top (schematic designator D7)
D7_21 "LED0" UV_LED 80,-40 r180 top (schematic designator D7)
D7_22 "LED0" UV_LED 100,-40 r180 top (schematic designator D7)
D7_23 "LED0" UV_LED 120,-40 r180 top (schematic designator D7)
D7_24 "LED0" UV_LED 140,-40 r180 top (schematic designator D7)
D7_25 "LED0" UV_LED 160,-40 r180 top (schematic designator D7)
D7_26 "LED0" UV_LED 40,-160 r180 top (schematic designator D7)
D7_27 "LED0" UV_LED 60,-160 r180 top (schematic designator D7)
D7_28 "LED0" UV_LED 80,-160 r180 top (schematic designator D7)
D7_29 "LED0" UV_LED 100,-160 r180 top (schematic designator D7)
D7_30 "LED0" UV_LED 120,-160 r180 top (schematic designator D7)
D7_31 "LED0" UV_LED 140,-160 r180 top (schematic designator D7)
D7_32 "LED0" UV_LED 160,-160 r180 top (schematic designator D7)
D7_33 "LED0" UV_LED 180,-40 r180 top (schematic designator D7)
D7_34 "LED0" UV_LED 180,-80 r180 top (schematic designator D7)
D7_35 "LED0" UV_LED 180,-120 r180 top (schematic designator D7)
D7_36 "LED0" UV_LED 180,-160 r180 top (schematic designator D7)
D8_1 "LED0" UV_LED 30,-120 r270 top (schematic designator D8)
D8_2 "LED0" UV_LED 40,-120 r270 top (schematic designator D8)
D8_3 "LED0" UV_LED 50,-120 r270 top (schematic designator D8)
D8_4 "LED0" UV_LED 60,-120 r270 top (schematic designator D8)
D8_5 "LED0" UV_LED 70,-120 r270 top (schematic designator D8)
D8_6 "LED0" UV_LED 80,-120 r270 top (schematic designator D8)
D8_7 "LED0" UV_LED 90,-120 r270 top (schematic designator D8)
D8_8 "LED0" UV_LED 100,-120 r270 top (schematic designator D8)
D8_9 "LED0" UV_LED 110,-120 r270 top (schematic designator D8)
D8_10 "LED0" UV_LED 120,-120 r270 top (schematic designator D8)
D8_11 "LED0" UV_LED 130,-120 r270 top (schematic designator D8)
D8_12 "LED0" UV_LED 140,-120 r270 top (schematic designator D8)
D8_13 "LED0" UV_LED 150,-120 r270 top (schematic designator D8)
D8_14 "LED0" UV_LED 160,-120 r270 top (schematic designator D8)
D8_15 "LED0" UV_LED 10,-40 r180 top (schematic designator D8)
D8_16 "LED0" UV_LED 10,-80 r180 top (schematic designator D8)
D8_17 "LED0" UV_LED 10,-120 r180 top (schematic designator D8)
D8_18 "LED0" UV_LED 10,-160 r180 top (schematic designator D8)
D8_19 "LED0" UV_LED 30,-40 r180 top (schematic designator D8)
D8_20 "LED0" UV_LED 50,-40 r180 top (schematic designator D8)
D8_21 "LED0" UV_LED 70,-40 r180 top (schematic designator D8)
D8_22 "LED0" UV_LED 90,-40 r180 top (schematic designator D8)
D8_23 "LED0" UV_LED 110,-40 r180 top (schematic designator D8)
D8_24 "LED0" UV_LED 130,-40 r180 top (schematic designator D8)
D8_25 "LED0" UV_LED 150,-40 r180 top (schematic designator D8)
D8_26 "LED0" UV_LED 30,-160 r180 top (schematic designator D8)
D8_27 "LED0" UV_LED 50,-160 r180 top (schematic designator D8)
D8_28 "LED0" UV_LED 70,-160 r180 top (schematic designator D8)
D8_29 "LED0" UV_LED 90,-160 r180 top (schematic designator D8)
D8_30 "LED0" UV_LED 110,-160 r180 top (schematic designator D8)
D8_31 "LED0" UV_LED 130,-160 r180 top (schematic designator D8)
D8_32 "LED0" UV_LED 150,-160 r180 top (schematic designator D8)
D8_33 "LED0" UV_LED 170,-40 r180 top (schematic designator D8)
D8_34 "LED0" UV_LED 170,-80 r180 top (schematic designator D8)
D8_35 "LED0" UV_LED 170,-120 r180 top (schematic designator D8)
D8_36 "LED0" UV_LED 170,-160 r180 top (schematic designator D8)
DR1_1 "NSI45020AT1G" NSI45020AT1G 30.687,-45.452 r180 top (schematic designator DR1)
DR1_2 "NSI45020AT1G" NSI45020AT1G 36.546,-48.603 r270 top (schematic designator DR1)
DR1_3 "NSI45020AT1G" NSI45020AT1G 46.546,-48.603 r270 top (schematic designator DR1)
DR1_4 "NSI45020AT1G" NSI45020AT1G 56.546,-48.603 r270 top (schematic designator DR1)
DR1_5 "NSI45020AT1G" NSI45020AT1G 66.546,-48.603 r270 top (schematic designator DR1)
DR1_6 "NSI45020AT1G" NSI45020AT1G 76.546,-48.603 r270 top (schematic designator DR1)
DR1_7 "NSI45020AT1G" NSI45020AT1G 86.546,-48.603 r270 top (schematic designator DR1)
DR1_8 "NSI45020AT1G" NSI45020AT1G 96.546,-48.603 r270 top (schematic designator DR1)
DR1_9 "NSI45020AT1G" NSI45020AT1G 106.546,-48.603 r270 top (schematic designator DR1)
DR1_10 "NSI45020AT1G" NSI45020AT1G 116.546,-48.603 r270 top (schematic designator DR1)
DR1_11 "NSI45020AT1G" NSI45020AT1G 126.546,-48.603 r270 top (schematic designator DR1)
DR1_12 "NSI45020AT1G" NSI45020AT1G 136.546,-48.603 r270 top (schematic designator DR1)
DR1_13 "NSI45020AT1G" NSI45020AT1G 146.546,-48.603 r270 top (schematic designator DR1)
DR1_14 "NSI45020AT1G" NSI45020AT1G 156.546,-48.603 r270 top (schematic designator DR1)
DR1_15 "NSI45020AT1G" NSI45020AT1G 6.175,-9.766 r270 top (schematic designator DR1)
DR1_16 "NSI45020AT1G" NSI45020AT1G 6.175,-49.766 r270 top (schematic designator DR1)
DR1_17 "NSI45020AT1G" NSI45020AT1G 6.175,-89.766 r270 top (schematic designator DR1)
DR1_18 "NSI45020AT1G" NSI45020AT1G 6.175,-129.766 r270 top (schematic designator DR1)
DR1_19 "NSI45020AT1G" NSI45020AT1G 26.175,-9.766 r270 top (schematic designator DR1)
DR1_20 "NSI45020AT1G" NSI45020AT1G 46.175,-9.766 r270 top (schematic designator DR1)
DR1_21 "NSI45020AT1G" NSI45020AT1G 66.175,-9.766 r270 top (schematic designator DR1)
DR1_22 "NSI45020AT1G" NSI45020AT1G 86.175,-9.766 r270 top (schematic designator DR1)
DR1_23 "NSI45020AT1G" NSI45020AT1G 106.175,-9.766 r270 top (schematic designator DR1)
DR1_24 "NSI45020AT1G" NSI45020AT1G 126.175,-9.766 r270 top (schematic designator DR1)
DR1_25 "NSI45020AT1G" NSI45020AT1G 146.175,-9.766 r270 top (schematic designator DR1)
DR1_26 "NSI45020AT1G" NSI45020AT1G 26.175,-129.766 r270 top (schematic designator DR1)
DR1_27 "NSI45020AT1G" NSI45020AT1G 46.175,-129.766 r270 top (schematic designator DR1)
DR1_28 "NSI45020AT1G" NSI45020AT1G 66.175,-129.766 r270 top (schematic designator DR1)
DR1_29 "NSI45020AT1G" NSI45020AT1G 86.175,-129.766 r270 top (schematic designator DR1)
DR1_30 "NSI45020AT1G" NSI45020AT1G 106.175,-129.766 r270 top (schematic designator DR1)
DR1_31 "NSI45020AT1G" NSI45020AT1G 126.175,-129.766 r270 top (schematic designator DR1)
DR1_32 "NSI45020AT1G" NSI45020AT1G 146.175,-129.766 r270 top (schematic designator DR1)
DR1_33 "NSI45020AT1G" NSI45020AT1G 166.175,-9.766 r270 top (schematic designator DR1)
DR1_34 "NSI45020AT1G" NSI45020AT1G 166.175,-49.766 r270 top (schematic designator DR1)
DR1_35 "NSI45020AT1G" NSI45020AT1G 166.175,-89.766 r270 top (schematic designator DR1)
DR1_36 "NSI45020AT1G" NSI45020AT1G 166.175,-129.766 r270 top (schematic designator DR1)

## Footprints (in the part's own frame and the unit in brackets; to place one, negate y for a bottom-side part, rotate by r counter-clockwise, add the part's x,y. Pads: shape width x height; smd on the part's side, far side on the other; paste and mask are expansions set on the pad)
NSI45020AT1G [mm]
  rect 0.91x1.22 smd: A(-1.635,0) K(1.635,0)
  silkscreen extent -1.35,-0.8 1.35,0.8
UV_LED [mm] "LED; 2 Leads"
  rect 1.5x2.6 smd: 1(-1.35,0) 2(1.35,0)
  silkscreen extent -1.78,-1.4 1.78,1.4

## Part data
D1_1 D1_2 D1_3 D1_4 D1_5 D1_6 D1_7 D1_8 D1_9 D1_10 D1_11 D1_12 D1_13 D1_14 D1_15 D1_16 D1_17 D1_18 D1_19 D1_20 D1_21 D1_22 D1_23 D1_24 D1_25 D1_26 D1_27 D1_28 D1_29 D1_30 D1_31 D1_32 D1_33 D1_34 D1_35 D1_36 D2_1 D2_2 D2_3 D2_4 D2_5 D2_6 D2_7 D2_8 D2_9 D2_10 D2_11 D2_12 D2_13 D2_14 D2_15 D2_16 D2_17 D2_18 D2_19 D2_20 D2_21 D2_22 D2_23 D2_24 D2_25 D2_26 D2_27 D2_28 D2_29 D2_30 D2_31 D2_32 D2_33 D2_34 D2_35 D2_36 D3_1 D3_2 D3_3 D3_4 D3_5 D3_6 D3_7 D3_8 D3_9 D3_10 D3_11 D3_12 D3_13 D3_14 D3_15 D3_16 D3_17 D3_18 D3_19 D3_20 D3_21 D3_22 D3_23 D3_24 D3_25 D3_26 D3_27 D3_28 D3_29 D3_30 D3_31 D3_32 D3_33 D3_34 D3_35 D3_36 D4_1 D4_2 D4_3 D4_4 D4_5 D4_6 D4_7 D4_8 D4_9 D4_10 D4_11 D4_12 D4_13 D4_14 D4_15 D4_16 D4_17 D4_18 D4_19 D4_20 D4_21 D4_22 D4_23 D4_24 D4_25 D4_26 D4_27 D4_28 D4_29 D4_30 D4_31 D4_32 D4_33 D4_34 D4_35 D4_36 D5_1 D5_2 D5_3 D5_4 D5_5 D5_6 D5_7 D5_8 D5_9 D5_10 D5_11 D5_12 D5_13 D5_14 D5_15 D5_16 D5_17 D5_18 D5_19 D5_20 D5_21 D5_22 D5_23 D5_24 D5_25 D5_26 D5_27 D5_28 D5_29 D5_30 D5_31 D5_32 D5_33 D5_34 D5_35 D5_36 D6_1 D6_2 D6_3 D6_4 D6_5 D6_6 D6_7 D6_8 D6_9 D6_10 D6_11 D6_12 D6_13 D6_14 D6_15 D6_16 D6_17 D6_18 D6_19 D6_20 D6_21 D6_22 D6_23 D6_24 D6_25 D6_26 D6_27 D6_28 D6_29 D6_30 D6_31 D6_32 D6_33 D6_34 D6_35 D6_36 D7_1 D7_2 D7_3 D7_4 D7_5 D7_6 D7_7 D7_8 D7_9 D7_10 D7_11 D7_12 D7_13 D7_14 D7_15 D7_16 D7_17 D7_18 D7_19 D7_20 D7_21 D7_22 D7_23 D7_24 D7_25 D7_26 D7_27 D7_28 D7_29 D7_30 D7_31 D7_32 D7_33 D7_34 D7_35 D7_36 D8_1 D8_2 D8_3 D8_4 D8_5 D8_6 D8_7 D8_8 D8_9 D8_10 D8_11 D8_12 D8_13 D8_14 D8_15 D8_16 D8_17 D8_18 D8_19 D8_20 D8_21 D8_22 D8_23 D8_24 D8_25 D8_26 D8_27 D8_28 D8_29 D8_30 D8_31 D8_32 D8_33 D8_34 D8_35 D8_36: "Typical INFRARED GaAs LED"

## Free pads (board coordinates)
  round 4.5 hole 0.4: 2(33.861,-84.849) 3(26.901,-84.874) 4(14.582,-55.029) 5(15.37,-75.146) 6(26.647,-74.892)
  round 7 hole 0.4: 7(65.188,-55.077) 8(125.188,-55.077) 9(125.188,-115.077) 10(65.188,-115.077) 11(190,0) 12(190,-170) 13(0,-170) 14(0,0)

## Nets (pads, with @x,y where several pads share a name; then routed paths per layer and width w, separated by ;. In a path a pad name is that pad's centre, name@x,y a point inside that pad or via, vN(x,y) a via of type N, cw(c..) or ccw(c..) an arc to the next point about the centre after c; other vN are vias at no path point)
GND: D8_1.2 D8_2.2 D8_3.2 D8_4.2 D8_5.2 D8_6.2 D8_7.2 D8_8.2 D8_9.2 D8_10.2 D8_11.2 D8_12.2 D8_13.2 D8_14.2 D8_15.2 D8_16.2 D8_17.2 D8_18.2 D8_19.2 D8_20.2 D8_21.2 D8_22.2 D8_23.2 D8_24.2 D8_25.2 D8_26.2 D8_27.2 D8_28.2 D8_29.2 D8_30.2 D8_31.2 D8_32.2 D8_33.2 D8_34.2 D8_35.2 D8_36.2 pad.3 pad.5 pad.6 | length 851.5
  Top Layer w0.8: 3.937,-120 D8_17.2@8.65,-120 ; 3.942,-80 D8_16.2@8.65,-80 ; 8.65,-163.132 D8_18.2@8.65,-160 ; 28.65,-163.132 D8_26.2@28.65,-160 ; 28.65,-43.32 D8_19.2@28.65,-40 ; 48.65,-163.132 D8_27.2@48.65,-160 ; 48.65,-43.244 D8_20.2@48.65,-40 ; 68.65,-163.132 D8_28.2@68.65,-160 ; 68.65,-43.235 D8_21.2@68.65,-40 ; 88.65,-163.132 D8_29.2@88.65,-160 ; 88.65,-43.32 D8_22.2@88.65,-40 ; 108.65,-163.132 D8_30.2@108.65,-160 ; 108.65,-43.32 D8_23.2@108.65,-40 ; 128.65,-163.132 D8_31.2@128.65,-160 ; 128.65,-43.32 D8_24.2@128.65,-40 ; 148.65,-163.132 D8_32.2@148.65,-160 ; 148.65,-43.32 D8_25.2@148.65,-40 ; 163.934,-80 D8_34.2@168.65,-80
  Top Layer w1: D8_15.2@8.65,-40 8.65,-42.646 9.324,-43.32 26.647,-43.32 ; pad.5@15.319,-75.146 6.632,-75.146 3.736,-78.042 3.736,-159.499 7.369,-163.132 8.65,-163.132 28.65,-163.132 48.65,-163.132 68.65,-163.132 88.65,-163.132 108.65,-163.132 128.65,-163.132 148.65,-163.132 167.375,-163.132 168.65,-161.856 D8_36.2@168.65,-160 ; pad.6@26.647,-74.892 26.647,-43.32 ; pad.3@26.901,-84.874 26.901,-120.51 27.741,-121.35 D8_1.2@30,-121.35 D8_2.2@39.833,-121.35 ; D8_2.2@40,-121.35 D8_3.2@50,-121.35 D8_4.2@60,-121.35 D8_5.2@70,-121.35 D8_5.2@70.167,-121.35 ; D8_6.2@80.167,-121.35 D8_5.2@70.167,-121.35 ; D8_29.2@88.623,-160 D8_29.2@88.65,-160 ; D8_7.2@90.167,-121.35 D8_5.2@70.167,-121.35 ; D8_8.2@100.167,-121.35 D8_5.2@70.167,-121.35 ; D8_31.2@128.603,-160 D8_31.2@128.65,-160 ; D8_14.2@160.167,-121.35 D8_5.2@70.167,-121.35 ; 163.934,-43.421 163.934,-80 163.934,-116.777 167.158,-120 D8_35.2@168.65,-120 ; 167.414,-43.32 148.65,-43.32 128.65,-43.32 108.65,-43.32 88.65,-43.32 28.65,-43.32 26.647,-43.32 ; 167.566,-43.167 168.65,-42.084 D8_33.2@168.65,-40
  Bottom Layer w1: pad.5@15.624,-74.892 pad.6@26.647,-74.892 ; pad.3@26.901,-84.874 pad.6@26.901,-75.146
NetD1_1_1: D1_1.1 DR1_1.K | length 3.6
  Top Layer w0.8: DR1_1.K@29.052,-45.452 29.052,-46.51 30,-47.457 D1_1.1@30,-48.65
NetD1_1_2: D1_1.2 D2_1.1 | length 7.3
  Top Layer w0.5: D2_1.1@30,-58.65 29.996,-58.65 29.996,-51.35 D1_1.2@30,-51.35
NetD1_2_1: D1_2.1 DR1_2.K | length 4.3
  Top Layer w0.8: DR1_2.K@36.546,-50.238 38.13,-48.654 D1_2.1@40.178,-48.654
NetD1_2_2: D1_2.2 D2_2.1 | length 7.3
  Top Layer w0.5: D2_2.1@40,-58.65 39.996,-58.65 39.996,-51.35 D1_2.2@40,-51.35
NetD1_3_1: D1_3.1 DR1_3.K | length 4.3
  Top Layer w0.8: DR1_3.K@46.546,-50.238 48.13,-48.654 D1_3.1@50.178,-48.654
NetD1_3_2: D1_3.2 D2_3.1 | length 7.3
  Top Layer w0.5: D2_3.1@50,-58.65 49.996,-58.65 49.996,-51.35 D1_3.2@50,-51.35
NetD1_4_1: D1_4.1 DR1_4.K | length 4.3
  Top Layer w0.8: DR1_4.K@56.546,-50.238 58.13,-48.654 D1_4.1@60.178,-48.654
NetD1_4_2: D1_4.2 D2_4.1 | length 7.3
  Top Layer w0.5: D2_4.1@60,-58.65 59.996,-58.65 59.996,-51.35 D1_4.2@60,-51.35
NetD1_5_1: D1_5.1 DR1_5.K | length 4.3
  Top Layer w0.8: DR1_5.K@66.546,-50.238 68.13,-48.654 D1_5.1@70.178,-48.654
NetD1_5_2: D1_5.2 D2_5.1 | length 7.3
  Top Layer w0.5: D2_5.1@70,-58.65 69.996,-58.65 69.996,-51.35 D1_5.2@70,-51.35
NetD1_6_1: D1_6.1 DR1_6.K | length 4.3
  Top Layer w0.8: DR1_6.K@76.546,-50.238 78.13,-48.654 D1_6.1@80.178,-48.654
NetD1_6_2: D1_6.2 D2_6.1 | length 7.3
  Top Layer w0.5: D2_6.1@80,-58.65 79.996,-58.65 79.996,-51.35 D1_6.2@80,-51.35
NetD1_7_1: D1_7.1 DR1_7.K | length 4.3
  Top Layer w0.8: DR1_7.K@86.546,-50.238 88.13,-48.654 D1_7.1@90.178,-48.654
NetD1_7_2: D1_7.2 D2_7.1 | length 7.3
  Top Layer w0.5: D2_7.1@90,-58.65 89.996,-58.65 89.996,-51.35 D1_7.2@90,-51.35
NetD1_8_1: D1_8.1 DR1_8.K | length 4.3
  Top Layer w0.8: DR1_8.K@96.546,-50.238 98.13,-48.654 D1_8.1@100.178,-48.654
NetD1_8_2: D1_8.2 D2_8.1 | length 7.3
  Top Layer w0.5: D2_8.1@100,-58.65 99.996,-58.65 99.996,-51.35 D1_8.2@100,-51.35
